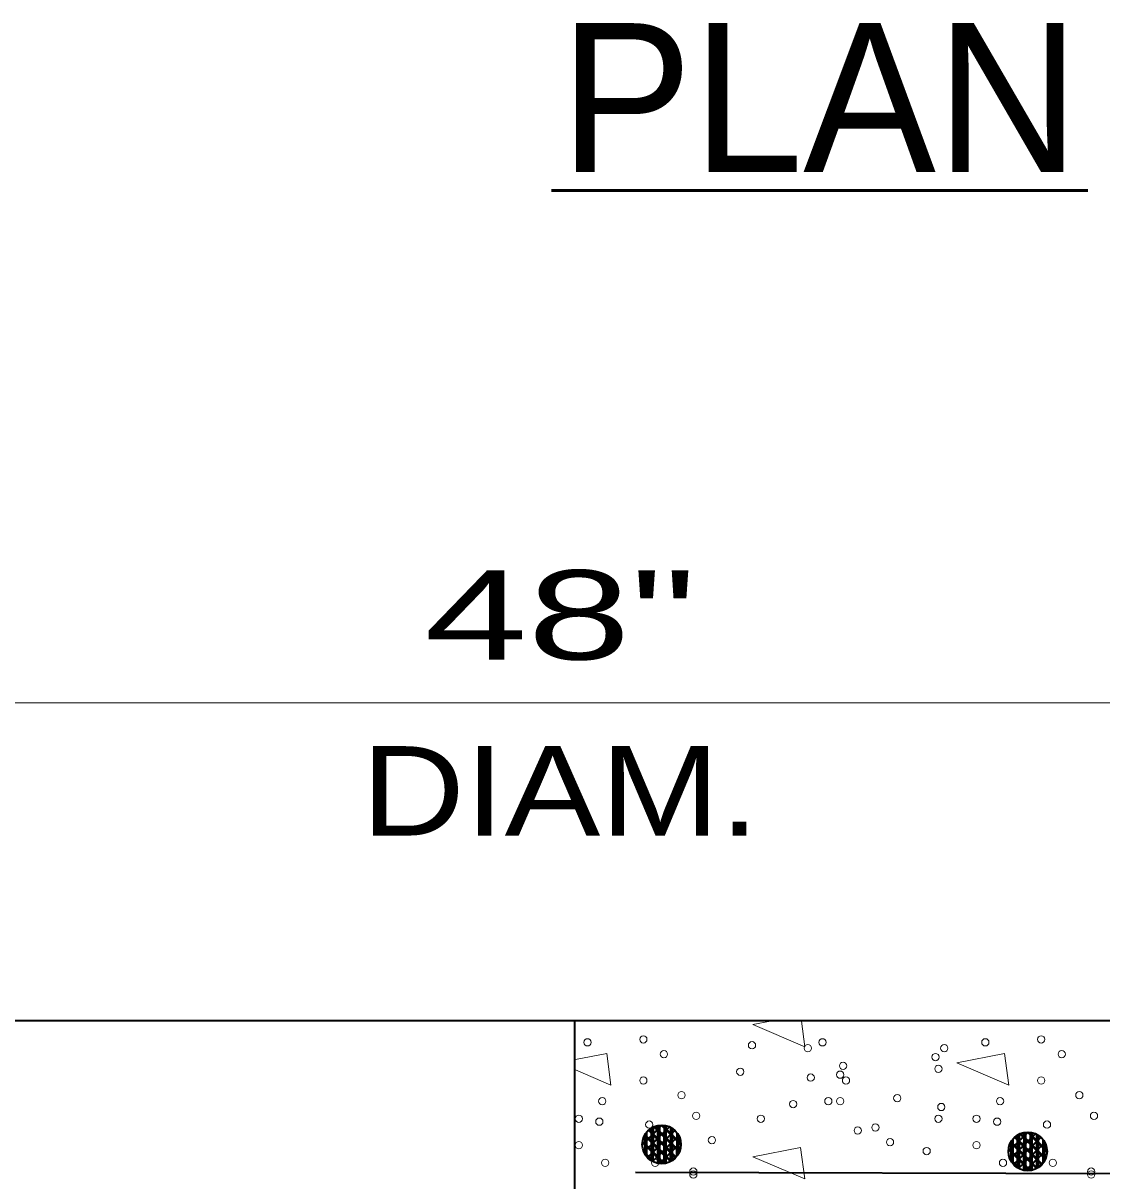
# Model space of a CAD drawing. Extents: x 5.1 to 20.2, y -16.7 to 4.3.
# Drawn here: x 11.185 to 12.743, y -3.2 to -1.529 of the extents above; entities that cross this region are included whole.
import ezdxf
from ezdxf.enums import TextEntityAlignment as Align

# ---------------------------------------------------------------- set-up
doc = ezdxf.new("R2010")
doc.units = 0
doc.header["$LTSCALE"] = 0.052
for name, color, linetype, lineweight in [('1', 7, 'Continuous', 35), ('10', 7, 'Continuous', 13), ('12', 7, 'Continuous', 53), ('13', 7, 'Continuous', 25), ('6', 7, 'Continuous', 13)]:
    doc.layers.add(name, color=color, linetype=linetype, lineweight=lineweight)

msp = doc.modelspace()

# ---------------------------------------------------------------- linework, layer by layer
at = {"layer": '1'}
for p, q in [((10.27058, -2.96833), (13.67525, -2.96833)), ((11.98133, -3.34717), (11.98133, -2.96833)), ((12.1035, -3.12317), (12.08258, -3.14392)), ((12.10717, -3.11958), (12.089, -3.13742)), ((12.09217, -3.1465), (12.09225, -3.12358)), ((12.09217, -3.13733), (12.09225, -3.12358)), ((12.09225, -3.12808), (12.09225, -3.12358)), ((12.09475, -3.1465), (12.09483, -3.12208)), ((12.09483, -3.13733), (12.09483, -3.12208)), ((12.09483, -3.12808), (12.09483, -3.12208)), ((12.113, -3.13942), (12.0955, -3.12192)), ((12.1065, -3.13292), (12.0955, -3.12192)), ((12.10008, -3.12633), (12.0955, -3.12192)), ((12.10717, -3.11958), (12.09558, -3.13092)), ((12.11658, -3.12317), (12.09558, -3.144)), ((12.11367, -3.13842), (12.09667, -3.12133)), ((12.10717, -3.13192), (12.09667, -3.12133)), ((12.10067, -3.12542), (12.09667, -3.12133)), ((12.12017, -3.145), (12.09933, -3.12408)), ((12.10133, -3.14658), (12.10142, -3.12)), ((12.10142, -3.13733), (12.10142, -3.12)), ((12.10142, -3.12817), (12.10142, -3.12)), ((12.11792, -3.12192), (12.10208, -3.1375)), ((12.104, -3.14658), (12.10408, -3.11958)), ((12.104, -3.13733), (12.10408, -3.11958)), ((12.104, -3.12817), (12.10408, -3.11958)), ((12.126, -3.1395), (12.10625, -3.11958)), ((12.1195, -3.13292), (12.10625, -3.11958)), ((12.113, -3.12642), (12.10625, -3.11958)), ((12.1065, -3.11983), (12.10625, -3.11958)), ((12.12675, -3.1385), (12.10783, -3.11958)), ((12.12025, -3.13192), (12.10783, -3.11958)), ((12.11375, -3.1255), (12.10783, -3.11958)), ((12.11058, -3.14658), (12.11067, -3.11983)), ((12.11058, -3.13733), (12.11067, -3.11983)), ((12.11067, -3.12817), (12.11067, -3.11983)), ((12.13317, -3.145), (12.11233, -3.12408)), ((12.11317, -3.14658), (12.11325, -3.12033)), ((12.11325, -3.13733), (12.11325, -3.12033)), ((12.11325, -3.12817), (12.11325, -3.12033)), ((12.11983, -3.14658), (12.11983, -3.12292)), ((12.11983, -3.13742), (12.11983, -3.12292)), ((12.11983, -3.12817), (12.11983, -3.12292)), ((12.12242, -3.14658), (12.1225, -3.12442)), ((12.12242, -3.13742), (12.1225, -3.12442)), ((12.1225, -3.12817), (12.1225, -3.12442)), ((12.097, -3.12967), (12.07892, -3.14767)), ((12.09042, -3.13617), (12.07892, -3.14767)), ((12.1, -3.15242), (12.08208, -3.13442)), ((12.0935, -3.14592), (12.08208, -3.13442)), ((12.087, -3.13933), (12.08208, -3.13442)), ((12.1035, -3.13617), (12.0825, -3.157)), ((12.10058, -3.1515), (12.08258, -3.13333)), ((12.09408, -3.14492), (12.08258, -3.13333)), ((12.08758, -3.13833), (12.08258, -3.13333)), ((12.08292, -3.15567), (12.083, -3.13275)), ((12.08292, -3.1465), (12.083, -3.13275)), ((12.08292, -3.16175), (12.083, -3.13533)), ((12.083, -3.13725), (12.083, -3.13275)), ((12.0855, -3.15575), (12.08558, -3.12917)), ((12.0855, -3.16492), (12.08558, -3.13533)), ((12.08558, -3.1465), (12.08558, -3.12917)), ((12.08558, -3.13725), (12.08558, -3.12917)), ((12.10642, -3.159), (12.08558, -3.138)), ((12.10708, -3.158), (12.08625, -3.13708)), ((12.10642, -3.14592), (12.08758, -3.127)), ((12.1, -3.13942), (12.08758, -3.127)), ((12.0935, -3.13283), (12.08758, -3.127)), ((12.10717, -3.14492), (12.0885, -3.12625)), ((12.10067, -3.13842), (12.0885, -3.12625)), ((12.09417, -3.13183), (12.0885, -3.12625)), ((12.11, -3.12967), (12.089, -3.1505)), ((12.09208, -3.16492), (12.09217, -3.13542)), ((12.09217, -3.15575), (12.09225, -3.12617)), ((12.11292, -3.1525), (12.09217, -3.13158)), ((12.11367, -3.1515), (12.09283, -3.13058)), ((12.09475, -3.15575), (12.09483, -3.12617)), ((12.09475, -3.16492), (12.09483, -3.13542)), ((12.1165, -3.13625), (12.0955, -3.15708)), ((12.1195, -3.146), (12.09867, -3.12508)), ((12.11942, -3.159), (12.09867, -3.138)), ((12.12017, -3.15808), (12.09925, -3.13708)), ((12.10133, -3.15575), (12.10142, -3.12617)), ((12.10133, -3.165), (12.10142, -3.13542)), ((12.123, -3.12975), (12.10208, -3.15058)), ((12.10392, -3.15575), (12.10408, -3.12625)), ((12.10392, -3.165), (12.104, -3.13542)), ((12.126, -3.1525), (12.10517, -3.13158)), ((12.12667, -3.1515), (12.10583, -3.13058)), ((12.12567, -3.12708), (12.10858, -3.144)), ((12.1295, -3.13625), (12.10858, -3.15708)), ((12.1105, -3.165), (12.11058, -3.13542)), ((12.11058, -3.15575), (12.11067, -3.12625)), ((12.13208, -3.15867), (12.11167, -3.13808)), ((12.1325, -3.146), (12.11175, -3.12508)), ((12.13258, -3.1575), (12.11233, -3.13717)), ((12.11317, -3.15583), (12.11325, -3.12625)), ((12.11317, -3.165), (12.11325, -3.13542)), ((12.13133, -3.13442), (12.11508, -3.15058)), ((12.13442, -3.14792), (12.11817, -3.13167)), ((12.13442, -3.14633), (12.11883, -3.13067)), ((12.11975, -3.15583), (12.11983, -3.12625)), ((12.11975, -3.165), (12.11983, -3.1355)), ((12.12233, -3.165), (12.12242, -3.1355)), ((12.12242, -3.15583), (12.1225, -3.12625)), ((12.13442, -3.14792), (12.12467, -3.13808)), ((12.13442, -3.14633), (12.12533, -3.13717)), ((12.12892, -3.164), (12.129, -3.1355)), ((12.129, -3.15583), (12.12908, -3.13083)), ((12.129, -3.14667), (12.12908, -3.13083)), ((12.129, -3.13742), (12.12908, -3.13083)), ((12.13158, -3.15583), (12.13167, -3.13508)), ((12.13158, -3.14667), (12.13167, -3.13508)), ((12.13158, -3.15983), (12.13167, -3.1355)), ((12.13167, -3.13742), (12.13167, -3.13508)), ((12.62575, -3.13975), (12.60767, -3.15775)), ((12.63225, -3.13325), (12.61133, -3.154)), ((12.61425, -3.16583), (12.61433, -3.13925)), ((12.61433, -3.15658), (12.61433, -3.13925)), ((12.61433, -3.14733), (12.61433, -3.13925)), ((12.63517, -3.156), (12.61633, -3.13708)), ((12.62875, -3.1495), (12.61633, -3.13708)), ((12.62225, -3.14292), (12.61633, -3.13708)), ((12.63592, -3.155), (12.61725, -3.13633)), ((12.62942, -3.1485), (12.61725, -3.13633)), ((12.62292, -3.14192), (12.61725, -3.13633)), ((12.63592, -3.12967), (12.61775, -3.1475)), ((12.63875, -3.13975), (12.61775, -3.16058)), ((12.62092, -3.15658), (12.621, -3.13367)), ((12.62092, -3.14742), (12.621, -3.13367)), ((12.62092, -3.16583), (12.621, -3.13625)), ((12.621, -3.13817), (12.621, -3.13367)), ((12.64242, -3.16158), (12.62158, -3.14067)), ((12.6235, -3.15658), (12.62358, -3.13217)), ((12.6235, -3.16583), (12.62358, -3.13625)), ((12.62358, -3.14742), (12.62358, -3.13217)), ((12.62358, -3.13817), (12.62358, -3.13217)), ((12.64175, -3.1495), (12.62425, -3.132)), ((12.63525, -3.143), (12.62425, -3.132)), ((12.62883, -3.13642), (12.62425, -3.132)), ((12.63592, -3.12967), (12.62433, -3.141)), ((12.64533, -3.13325), (12.62433, -3.15408)), ((12.64242, -3.1485), (12.62542, -3.13142)), ((12.63592, -3.142), (12.62542, -3.13142)), ((12.62942, -3.1355), (12.62542, -3.13142)), ((12.64825, -3.15608), (12.62742, -3.13517)), ((12.64892, -3.15508), (12.62808, -3.13417)), ((12.63008, -3.15667), (12.63017, -3.13008)), ((12.63008, -3.16583), (12.63017, -3.13625)), ((12.63017, -3.14742), (12.63017, -3.13008)), ((12.63017, -3.13825), (12.63017, -3.13008)), ((12.64667, -3.132), (12.63083, -3.14758)), ((12.65175, -3.13983), (12.63083, -3.16067)), ((12.63267, -3.16583), (12.63283, -3.13633)), ((12.63275, -3.15667), (12.63283, -3.12967)), ((12.63275, -3.14742), (12.63283, -3.12967)), ((12.63275, -3.13825), (12.63283, -3.12967)), ((12.65542, -3.16158), (12.63458, -3.14067)), ((12.65475, -3.14958), (12.635, -3.12967)), ((12.64825, -3.143), (12.635, -3.12967)), ((12.64175, -3.1365), (12.635, -3.12967)), ((12.63525, -3.12992), (12.635, -3.12967)), ((12.6555, -3.14858), (12.63658, -3.12967)), ((12.649, -3.142), (12.63658, -3.12967)), ((12.6425, -3.13558), (12.63658, -3.12967)), ((12.65442, -3.13717), (12.63733, -3.15408)), ((12.63933, -3.15667), (12.63942, -3.12992)), ((12.63933, -3.14742), (12.63942, -3.12992)), ((12.63933, -3.16583), (12.63942, -3.13633)), ((12.63942, -3.13825), (12.63942, -3.12992)), ((12.66125, -3.15608), (12.6405, -3.13517)), ((12.66192, -3.15508), (12.64108, -3.13417)), ((12.64192, -3.15667), (12.642, -3.13042)), ((12.64192, -3.16592), (12.642, -3.13633)), ((12.642, -3.14742), (12.642, -3.13042)), ((12.642, -3.13825), (12.642, -3.13042)), ((12.66317, -3.15642), (12.64758, -3.14075)), ((12.6485, -3.16592), (12.64858, -3.13633)), ((12.64858, -3.15667), (12.64858, -3.133)), ((12.64858, -3.1475), (12.64858, -3.133)), ((12.64858, -3.13825), (12.64858, -3.133)), ((12.65117, -3.15667), (12.65125, -3.1345)), ((12.65117, -3.1475), (12.65125, -3.1345)), ((12.65117, -3.16592), (12.65125, -3.13633)), ((12.65125, -3.13825), (12.65125, -3.1345)), ((12.65775, -3.16592), (12.65783, -3.14092)), ((12.65775, -3.15675), (12.65783, -3.14092)), ((12.65775, -3.1475), (12.65783, -3.14092)), ((12.08392, -3.14258), (12.07892, -3.14767)), ((12.09992, -3.16542), (12.079, -3.1445)), ((12.09342, -3.159), (12.079, -3.1445)), ((12.08692, -3.15242), (12.079, -3.1445)), ((12.08042, -3.14583), (12.079, -3.1445)), ((12.09408, -3.158), (12.07917, -3.14292)), ((12.0875, -3.15142), (12.07917, -3.14292)), ((12.08108, -3.14483), (12.07917, -3.14292)), ((12.10058, -3.1645), (12.07975, -3.14358)), ((12.09617, -3.17308), (12.08083, -3.15767)), ((12.094, -3.171), (12.08083, -3.15767)), ((12.0875, -3.1645), (12.08083, -3.15767)), ((12.08108, -3.15792), (12.08083, -3.15767)), ((12.09692, -3.14258), (12.08117, -3.15842)), ((12.09042, -3.14917), (12.08117, -3.15842)), ((12.08383, -3.15567), (12.08117, -3.15842)), ((12.08292, -3.16175), (12.08292, -3.14458)), ((12.08292, -3.16175), (12.08292, -3.15375)), ((12.0855, -3.16542), (12.08558, -3.14458)), ((12.0855, -3.16542), (12.0855, -3.15383)), ((12.10633, -3.172), (12.08558, -3.151)), ((12.10342, -3.14917), (12.08625, -3.16625)), ((12.10708, -3.17108), (12.08625, -3.15)), ((12.09692, -3.15567), (12.08625, -3.16625)), ((12.11, -3.14267), (12.089, -3.16358)), ((12.11292, -3.1655), (12.09208, -3.1445)), ((12.09208, -3.171), (12.09217, -3.14458)), ((12.09208, -3.171), (12.09217, -3.15383)), ((12.10942, -3.17508), (12.09208, -3.15758)), ((12.11358, -3.16458), (12.09275, -3.14358)), ((12.11083, -3.17483), (12.09275, -3.15658)), ((12.10992, -3.15575), (12.09358, -3.17192)), ((12.09467, -3.1725), (12.09475, -3.14458)), ((12.09467, -3.1725), (12.09475, -3.15383)), ((12.1165, -3.14917), (12.0955, -3.17008)), ((12.11942, -3.172), (12.09858, -3.15108)), ((12.12008, -3.17108), (12.09925, -3.15008)), ((12.10125, -3.17417), (12.10142, -3.14467)), ((12.10125, -3.17467), (12.10133, -3.15383)), ((12.12292, -3.14267), (12.102, -3.16358)), ((12.12292, -3.15575), (12.10358, -3.175)), ((12.10392, -3.17417), (12.104, -3.14467)), ((12.10392, -3.175), (12.104, -3.15383)), ((12.1195, -3.17208), (12.10508, -3.15758)), ((12.12592, -3.1655), (12.10517, -3.14458)), ((12.12667, -3.16458), (12.10575, -3.14367)), ((12.1205, -3.1715), (12.10575, -3.15658)), ((12.1295, -3.14925), (12.1085, -3.17017)), ((12.1105, -3.17425), (12.11058, -3.14467)), ((12.1105, -3.17492), (12.11058, -3.15383)), ((12.12692, -3.1665), (12.11167, -3.15108)), ((12.12767, -3.16558), (12.11225, -3.15008)), ((12.11308, -3.17425), (12.11317, -3.14467)), ((12.11308, -3.17442), (12.11317, -3.15392)), ((12.13433, -3.14442), (12.11508, -3.16367)), ((12.13208, -3.15867), (12.11808, -3.14458)), ((12.13258, -3.1575), (12.11883, -3.14367)), ((12.11975, -3.17192), (12.11983, -3.14467)), ((12.11975, -3.17192), (12.11975, -3.15392)), ((12.13433, -3.14442), (12.12158, -3.15717)), ((12.12233, -3.17033), (12.12242, -3.14467)), ((12.12233, -3.17033), (12.12242, -3.15392)), ((12.12892, -3.164), (12.129, -3.14475)), ((12.12892, -3.164), (12.129, -3.15392)), ((12.13158, -3.15983), (12.13158, -3.14475)), ((12.13158, -3.15983), (12.13158, -3.15392)), ((12.61917, -3.14625), (12.60767, -3.15775)), ((12.61267, -3.15267), (12.60767, -3.15775)), ((12.62867, -3.1755), (12.60775, -3.15458)), ((12.62217, -3.16908), (12.60775, -3.15458)), ((12.61567, -3.1625), (12.60775, -3.15458)), ((12.60917, -3.15592), (12.60775, -3.15458)), ((12.62283, -3.16808), (12.60792, -3.153)), ((12.61625, -3.1615), (12.60792, -3.153)), ((12.60983, -3.15492), (12.60792, -3.153)), ((12.62933, -3.17458), (12.6085, -3.15367)), ((12.62567, -3.15267), (12.60992, -3.1685)), ((12.62875, -3.1625), (12.61083, -3.1445)), ((12.62225, -3.156), (12.61083, -3.1445)), ((12.61575, -3.14942), (12.61083, -3.1445)), ((12.63225, -3.14625), (12.61125, -3.16708)), ((12.62933, -3.16158), (12.61133, -3.14342)), ((12.62283, -3.155), (12.61133, -3.14342)), ((12.61633, -3.14842), (12.61133, -3.14342)), ((12.61167, -3.16575), (12.61175, -3.14283)), ((12.61167, -3.15658), (12.61175, -3.14283)), ((12.61167, -3.17183), (12.61175, -3.14542)), ((12.61167, -3.17183), (12.61167, -3.15467)), ((12.61175, -3.14733), (12.61175, -3.14283)), ((12.61425, -3.175), (12.61433, -3.14542)), ((12.61425, -3.1755), (12.61433, -3.15467)), ((12.63517, -3.16908), (12.61433, -3.14808)), ((12.63583, -3.16808), (12.615, -3.14717)), ((12.63875, -3.15275), (12.61775, -3.17367)), ((12.62083, -3.175), (12.62092, -3.1455)), ((12.64167, -3.17558), (12.62083, -3.15458)), ((12.62083, -3.18108), (12.62092, -3.15467)), ((12.64167, -3.16258), (12.62092, -3.14167)), ((12.64233, -3.17467), (12.6215, -3.15367)), ((12.62342, -3.18258), (12.6235, -3.15467)), ((12.6235, -3.175), (12.62358, -3.1455)), ((12.64525, -3.14633), (12.62425, -3.16717)), ((12.64817, -3.16908), (12.62742, -3.14808)), ((12.64892, -3.16817), (12.628, -3.14717)), ((12.63, -3.18425), (12.63017, -3.15475)), ((12.63008, -3.17508), (12.63017, -3.1455)), ((12.65167, -3.15275), (12.63075, -3.17367)), ((12.63267, -3.17508), (12.63275, -3.1455)), ((12.63267, -3.18425), (12.63275, -3.15475)), ((12.65475, -3.16258), (12.63392, -3.14167)), ((12.65467, -3.17558), (12.63392, -3.15467)), ((12.65542, -3.17467), (12.6345, -3.15375)), ((12.65825, -3.14633), (12.63733, -3.16717)), ((12.63925, -3.17508), (12.63933, -3.1455)), ((12.63925, -3.18433), (12.63933, -3.15475)), ((12.66083, -3.16875), (12.64042, -3.14817)), ((12.66133, -3.16758), (12.64108, -3.14725)), ((12.64183, -3.18433), (12.64192, -3.15475)), ((12.64192, -3.17508), (12.642, -3.1455)), ((12.66008, -3.1445), (12.64383, -3.16067)), ((12.66308, -3.1545), (12.64383, -3.17375)), ((12.66083, -3.16875), (12.64683, -3.15467)), ((12.66317, -3.158), (12.64692, -3.14175)), ((12.66133, -3.16758), (12.64758, -3.15375)), ((12.6485, -3.17508), (12.64858, -3.14558)), ((12.6485, -3.182), (12.64858, -3.15475)), ((12.66308, -3.1545), (12.65033, -3.16725)), ((12.65108, -3.17508), (12.65117, -3.14558)), ((12.65108, -3.18042), (12.65117, -3.15475)), ((12.66317, -3.158), (12.65342, -3.14817)), ((12.66317, -3.15642), (12.65408, -3.14725)), ((12.65767, -3.17408), (12.65775, -3.14558)), ((12.65767, -3.17408), (12.65775, -3.15483)), ((12.66033, -3.16592), (12.66042, -3.14517)), ((12.66033, -3.15675), (12.66042, -3.14517)), ((12.66033, -3.16992), (12.66042, -3.14558)), ((12.66033, -3.16992), (12.66033, -3.15483)), ((12.66042, -3.1475), (12.66042, -3.14517)), ((12.09308, -3.17167), (12.08225, -3.16075)), ((12.09308, -3.17167), (12.08225, -3.16075)), ((12.08692, -3.16542), (12.08225, -3.16075)), ((12.09308, -3.17167), (12.0855, -3.16408)), ((12.09617, -3.17308), (12.08617, -3.16308)), ((12.09033, -3.16217), (12.08625, -3.16625)), ((12.09308, -3.17167), (12.092, -3.17058)), ((12.09617, -3.17308), (12.09267, -3.16967)), ((12.10342, -3.16225), (12.09358, -3.17192)), ((12.09683, -3.16875), (12.09358, -3.17192)), ((12.10942, -3.17508), (12.09858, -3.16408)), ((12.11083, -3.17483), (12.09917, -3.16308)), ((12.11642, -3.16225), (12.10358, -3.175)), ((12.10992, -3.16875), (12.10358, -3.175)), ((12.13125, -3.1605), (12.11975, -3.172)), ((12.12942, -3.16233), (12.11975, -3.172)), ((12.12283, -3.16883), (12.11975, -3.172)), ((12.13125, -3.1605), (12.12158, -3.17017)), ((12.13125, -3.1605), (12.12808, -3.16367)), ((12.62492, -3.18317), (12.60958, -3.16775)), ((12.62275, -3.18108), (12.60958, -3.16775)), ((12.61625, -3.17458), (12.60958, -3.16775)), ((12.60983, -3.168), (12.60958, -3.16775)), ((12.61917, -3.15925), (12.60992, -3.1685)), ((12.61258, -3.16575), (12.60992, -3.1685)), ((12.62183, -3.18175), (12.611, -3.17083)), ((12.62183, -3.18175), (12.611, -3.17083)), ((12.61567, -3.1755), (12.611, -3.17083)), ((12.61167, -3.17183), (12.61167, -3.16383)), ((12.61425, -3.1755), (12.61425, -3.16392)), ((12.62183, -3.18175), (12.61425, -3.17417)), ((12.63508, -3.18208), (12.61433, -3.16108)), ((12.62492, -3.18317), (12.61492, -3.17317)), ((12.63217, -3.15925), (12.615, -3.17633)), ((12.63583, -3.18117), (12.615, -3.16008)), ((12.62567, -3.16575), (12.615, -3.17633)), ((12.61908, -3.17225), (12.615, -3.17633)), ((12.62083, -3.18108), (12.62092, -3.16392)), ((12.63817, -3.18517), (12.62083, -3.16767)), ((12.63958, -3.18492), (12.6215, -3.16667)), ((12.63867, -3.16583), (12.62233, -3.182)), ((12.63217, -3.17233), (12.62233, -3.182)), ((12.62342, -3.18258), (12.6235, -3.16392)), ((12.64525, -3.15925), (12.62425, -3.18017)), ((12.64817, -3.18208), (12.62733, -3.16117)), ((12.63817, -3.18517), (12.62733, -3.17417)), ((12.63958, -3.18492), (12.62792, -3.17317)), ((12.64883, -3.18117), (12.628, -3.16017)), ((12.63, -3.18475), (12.63008, -3.16392)), ((12.65167, -3.16583), (12.63233, -3.18508)), ((12.64517, -3.17233), (12.63233, -3.18508)), ((12.63267, -3.18508), (12.63275, -3.16392)), ((12.64825, -3.18217), (12.63383, -3.16767)), ((12.64925, -3.18158), (12.6345, -3.16667)), ((12.65825, -3.15933), (12.63725, -3.18025)), ((12.63925, -3.185), (12.63933, -3.16392)), ((12.65567, -3.17658), (12.64042, -3.16117)), ((12.65642, -3.17567), (12.641, -3.16017)), ((12.64183, -3.1845), (12.64192, -3.164)), ((12.6485, -3.182), (12.6485, -3.164)), ((12.66, -3.17058), (12.6485, -3.18208)), ((12.65817, -3.17242), (12.6485, -3.18208)), ((12.66, -3.17058), (12.65033, -3.18025)), ((12.65108, -3.18042), (12.65117, -3.164)), ((12.66, -3.17058), (12.65683, -3.17375)), ((12.65767, -3.17408), (12.65775, -3.164)), ((12.66033, -3.16992), (12.66033, -3.164)), ((12.06892, -3.18733), (13.56933, -3.192)), ((12.62183, -3.18175), (12.62075, -3.18067)), ((12.62492, -3.18317), (12.62142, -3.17975)), ((12.62558, -3.17883), (12.62233, -3.182)), ((12.63867, -3.17883), (12.63233, -3.18508)), ((12.65158, -3.17892), (12.6485, -3.18208))]:
    msp.add_line(p, q, dxfattribs=at)
for centre in [(12.10669, -3.14735), (12.63544, -3.15743)]:
    msp.add_circle(centre, 0.02789, dxfattribs=at)
at = {"layer": '10'}
msp.add_line((10.45475, -2.51), (13.44833, -2.51), dxfattribs=at)
at = {"layer": '12'}
msp.add_line((11.94758, -1.77067), (12.72242, -1.77067), dxfattribs=at)
at = {"layer": '6'}
msp.add_line((12.2385, -2.97433), (12.26383, -2.96942), dxfattribs=at)
for points in [[(12.30858, -2.96933), (12.31342, -3.00642), (12.2385, -2.97433)], [(11.98233, -3.02492), (12.0275, -3.016), (12.0335, -3.06158), (11.98233, -3.03967)]]:
    msp.add_lwpolyline(points, dxfattribs=at)
for points in [[(12.53308, -3.0295), (12.602, -3.016), (12.608, -3.06158)], [(12.2385, -3.16517), (12.30742, -3.15167), (12.31342, -3.19725)]]:
    msp.add_lwpolyline(points, close=True, dxfattribs=at)
for centre in [(12.08033, -2.99575), (12.65483, -2.99575), (11.99975, -3), (12.23725, -3.00425), (12.31783, -3.0085), (12.33908, -3), (12.51492, -3.0085), (12.57425, -3), (12.11008, -3.017), (12.50217, -3.02125), (12.68458, -3.017), (12.22033, -3.04242), (12.36875, -3.03392), (12.50642, -3.03817), (12.08033, -3.05517), (12.32208, -3.05092), (12.3645, -3.04667), (12.373, -3.05517), (12.65483, -3.05517), (12.1355, -3.07633), (12.71, -3.07633), (12.021, -3.08483), (12.29667, -3.08908), (12.3475, -3.08483), (12.3645, -3.08483), (12.44708, -3.08058), (12.51067, -3.09333), (12.5955, -3.08483), (11.98708, -3.11025), (12.15667, -3.106), (12.25, -3.11025), (12.50642, -3.11025), (12.56158, -3.11025), (12.73117, -3.106), (12.01675, -3.1145), (12.08883, -3.11875), (12.38992, -3.12725), (12.41542, -3.123), (12.59125, -3.1145), (12.66333, -3.11875), (12.17942, -3.14125), (12.43658, -3.14417), (11.98708, -3.14842), (12.4895, -3.15692), (12.56158, -3.14842), (12.02525, -3.17392), (12.09733, -3.17392), (12.59975, -3.17392), (12.67183, -3.17392), (12.1525, -3.18658), (12.1525, -3.19083), (12.727, -3.18658), (12.727, -3.19083)]:
    msp.add_circle(centre, 0.00525, dxfattribs=at)

# ---------------------------------------------------------------- texts
at = {"layer": '12'}
msp.add_text('PLAN', height=0.215, dxfattribs=at).set_placement((12.335, -1.74392), align=Align.CENTER)
at = {"layer": '12', "width": 1.2}
msp.add_text('DIAM.', height=0.129, dxfattribs=at).set_placement((11.96054, -2.7015), align=Align.CENTER)
at = {"layer": '13', "width": 1.55}
msp.add_text('48"', height=0.129, dxfattribs=at).set_placement((11.9605, -2.4475), align=Align.CENTER)

doc.saveas('drawing.dxf')
